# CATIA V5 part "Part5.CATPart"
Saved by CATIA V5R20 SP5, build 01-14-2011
Part number: 右
Bounding box of the stored display mesh (mm): x -8.78 to 57.322, y -10 to 10, z -74.832 to -34.077
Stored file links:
  E:\180511232\很靠后、\Part5.CATPart
  Part4.CATPart
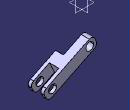
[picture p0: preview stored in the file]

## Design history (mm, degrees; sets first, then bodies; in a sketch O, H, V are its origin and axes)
Body1 (main body)
Body2
  Sketch1 on zx-plane, origin (0, 0, 0), H (-1, 0, 0), V (0, 0, 1)
    circle A1 centre (0, -42.6263) radius 5
    point P1 (0, -42.6263)
    line L1 (3.9059, -32.3796) -> (10.4771, -45.8636)
    line L2 (10.4771, -45.8636) -> (-52.4483, -76.5295)
    line L3 (-52.4483, -76.5295) -> (-59.0196, -63.0454)
    line L4 (-59.0196, -63.0454) -> (3.9059, -32.3796)
    circle A2 centre (-46.7446, -65.4066) radius 5
    point P6 (-46.7446, -65.4066)
    radius A1 = 5
    length L4 = 70
    length L3 = 15
    distance P1 L2 = 7.5
    distance P1 L1 = 8
    radius A2 = 5
    distance P6 L4 = 7.5
    distance P6 L3 = 10
    coincidence: P1 V
    parallelism: L4 L2, L1 L3
    perpendicularity: L1 L2
  Pad1: profile Sketch1, direction (0, 1, 0), length 10, mirrored extent
  Sketch2 on start face of Pad1, origin (0, -10, 0), H (1, 0, 0), V (0, 0, 1)
    line L1 (-3.9059, -32.3796) -> (-10.4771, -45.8636)
    point P1 (-3.9059, -32.3796)
    point P2 (-10.4771, -45.8636)
    line L2 (-10.4771, -45.8636) -> (16.4909, -59.0061)
    line L3 (16.4909, -59.0061) -> (23.0622, -45.5221)
    line L4 (23.0622, -45.5221) -> (-3.9059, -32.3796)
    point P3 (16.4909, -59.0061)
    reference projected point E1 (-10.4771, -45.8636) from vertex [face of Pad1 from Sketch1.L1 | start face of Pad1 | face of Pad1 from Sketch1.L2]
    reference projected line E2 (52.4483, -76.5295) -> (-10.4771, -45.8636) from edge [start face of Pad1 | face of Pad1 from Sketch1.L2]
    reference projected point E3 (-3.9059, -32.3796) from vertex [face of Pad1 from Sketch1.L1 | start face of Pad1 | face of Pad1 from Sketch1.L4]
    distance P2 E1 = 0
    distance P3 E2 = 0
    distance P1 E3 = 0
    length L4 = 30
    parallelism: L4 L2, L1 L3
  Pocket1: profile Sketch2, direction (0, 1, 0), length 10
  Sketch3 on face of Pad1 from Sketch1.L4, origin (-13.501, 0, -27.7036), H (0, 1, 0), V (-0.8989, 0, 0.4381)
    line L1 (-6, -53.62) -> (6, -53.62)
    line L2 (6, -53.62) -> (6, -93.62)
    line L3 (6, -93.62) -> (-6, -93.62)
    line L4 (-6, -93.62) -> (-6, -53.62)
    reference projected line E1 (-10, -10.6739) -> (-10, -80.6739) from edge [start face of Pad1 | face of Pad1 from Sketch1.L4]
    length L4 = 40
    length L3 = 12
    distance L4 E1 = 4
    horizontal: L1 H, L3 H
    vertical: L2 V, L4 V
  Pocket2: profile Sketch3, direction (-0.4381, 0, -0.8989), length 30
  Fillet1: radius 5, on edge [face of Pad1 from Sketch1.L4 | face of Pad1 from Sketch1.L1]
  Fillet2: radius 5, on edge [face of Pad1 from Sketch1.L1 | face of Pad1 from Sketch1.L2]
  Fillet3: radius 5, on edge [face of Pad1 from Sketch1.L3 | face of Pad1 from Sketch1.L4] (x2); edge [face of Pad1 from Sketch1.L2 | face of Pad1 from Sketch1.L3] (x2)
